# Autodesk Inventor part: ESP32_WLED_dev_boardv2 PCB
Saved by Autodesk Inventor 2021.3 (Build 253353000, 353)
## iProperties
Created: 2022-06
Part Number: ESP32_WLED_dev_boardv2 PCB
Material: Generic
Document SubType Name: Modeling
Designer: Administrator
Density: 1 g/cm^3
Appearance: Default
Title: ESP32_WLED_dev_boardv2 PCB
Author: Administrator
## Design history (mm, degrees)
feature "Body1"
body "Solid1"
